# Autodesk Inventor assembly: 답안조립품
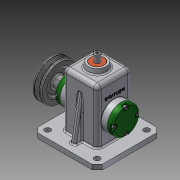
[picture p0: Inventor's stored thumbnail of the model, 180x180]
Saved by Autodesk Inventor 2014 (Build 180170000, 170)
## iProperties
Created: 2016-02
Part Number: 답안조립품
Document SubType Name: Assembly
Designer: HGY
Author: HGY
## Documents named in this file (16)
- C:\Users\Administrator\Desktop\460211V1030\답안조립품.iam
- C:\Users\Administrator\Desktop\460211V1030\1-본체.ipt
- C:\Users\Administrator\Desktop\460211V1030\V벨트풀리.ipt
- C:\Users\Administrator\Desktop\460211V1030\고정핀 1.2 x 10.ipt
- C:\Users\Administrator\Desktop\460211V1030\뒤커버.ipt
- C:\Users\Administrator\Desktop\460211V1030\링크.ipt
- C:\Users\Administrator\Desktop\460211V1030\멈춤나사 M3x8.ipt
- C:\Users\Administrator\Desktop\460211V1030\베어링 12 x 32 x 10.ipt
- C:\Users\Administrator\Desktop\460211V1030\볼트 M4 x 12.ipt
- C:\Users\Administrator\Desktop\460211V1030\부시.ipt
- C:\Users\Administrator\Desktop\460211V1030\슬라이드.ipt
- C:\Users\Administrator\Desktop\460211V1030\앞커버.ipt
- C:\Users\Administrator\Desktop\460211V1030\오일실 12 25 7.ipt
- C:\Users\Administrator\Desktop\460211V1030\키 4 x 4 x 10.ipt
- C:\Users\Administrator\Desktop\460211V1030\편심축.ipt
- C:\Users\Administrator\Desktop\460211V1030\핀 5 x 18.ipt
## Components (12 placed, 5 different names)
1. 1-본체:1 — 각도:2, 각도:3
2. V벨트풀리:1
3. 고정핀 1.2 x 10:1 — 각도:1
4. 핀 5 x 18:1 — 각도:1
5. ISO 4762 M4 x 12:1 — 각도:2
6. ISO 4762 M4 x 12:3
7. ISO 4762 M4 x 12:4
8. ISO 4762 M4 x 12:5
9. ISO 4762 M4 x 12:2 — 각도:3
10. ISO 4762 M4 x 12:6
11. ISO 4762 M4 x 12:7
12. ISO 4762 M4 x 12:8
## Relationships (3: Angle 3)
- 각도:1 [Angle]: 고정핀 1.2 x 10:1 ↔ 핀 5 x 18:1
- 각도:2 [Angle]: 1-본체:1 ↔ ISO 4762 M4 x 12:1
- 각도:3 [Angle]: 1-본체:1 ↔ ISO 4762 M4 x 12:2
